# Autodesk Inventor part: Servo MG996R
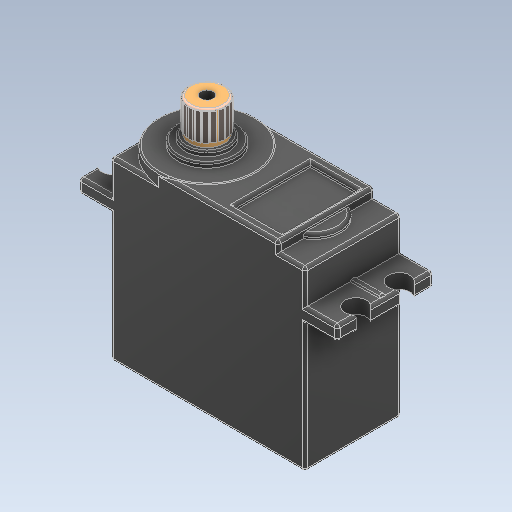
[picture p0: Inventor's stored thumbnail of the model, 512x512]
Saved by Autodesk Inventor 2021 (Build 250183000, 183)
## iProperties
Created: 2020-05
Part Number: Servo MG996R
Material: Generic
Description: STEP AP214
Document SubType Name: Modeling
Designer: alolo
Density: 1 g/cm^3
Appearance: Default
Sending System: SolidWorks 2010
Preprocessor: SwSTEP 2.0
Title: Servo MG996R.STEP
Revision Number: ANY
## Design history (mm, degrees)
feature "MatrizC0"
body "Solid1"
